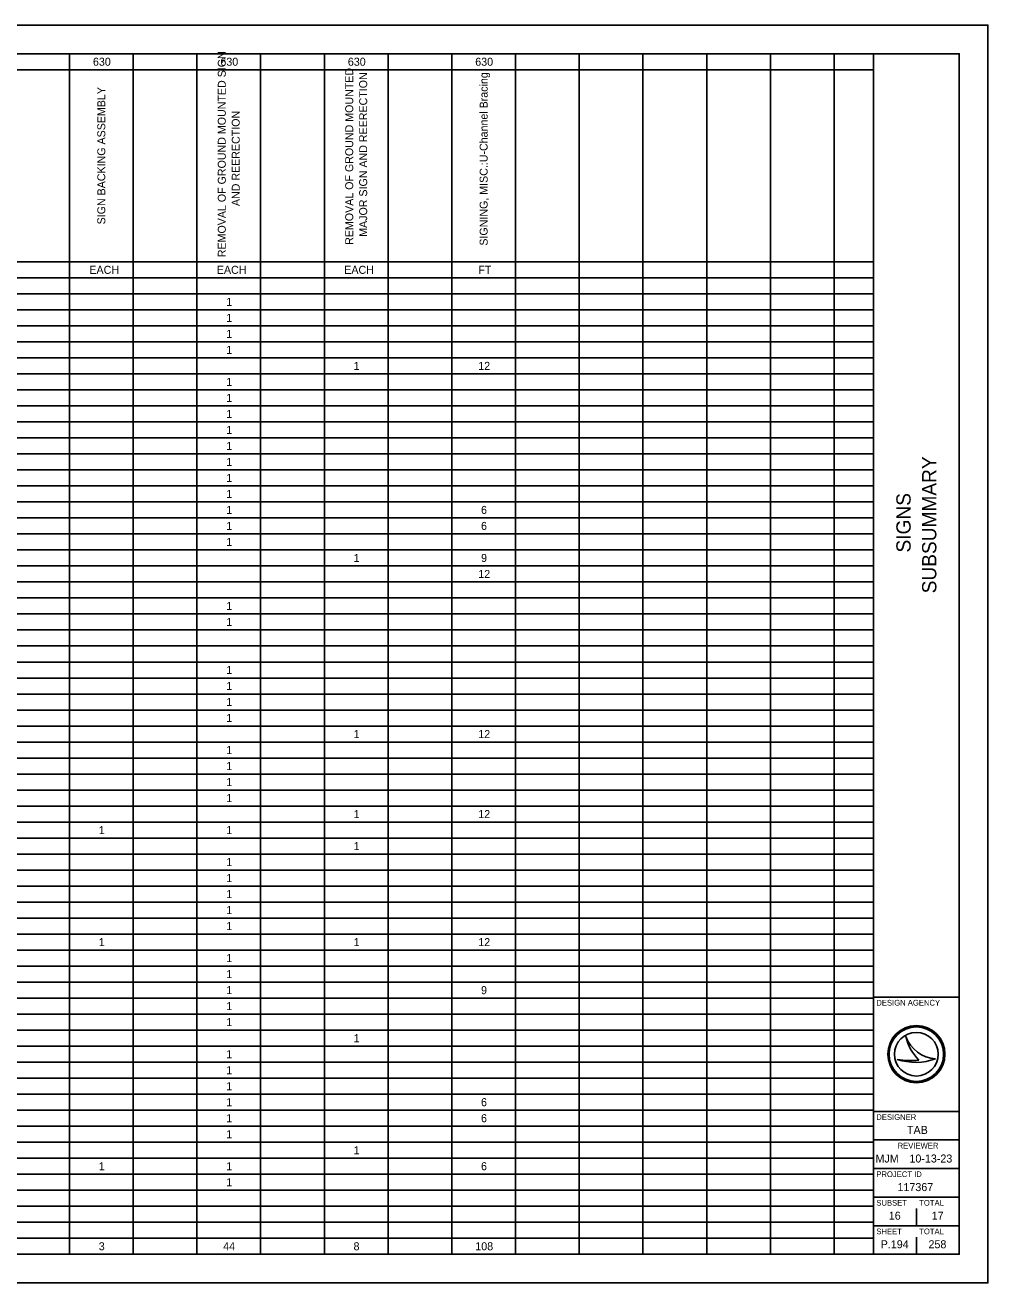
# Model space of a CAD drawing. Extents: x 0 to 34, y 0 to 22.
# Drawn here: x 17.16 to 34, y 0 to 22 of the extents above; entities that cross this region are included whole.
import ezdxf

# ---------------------------------------------------------------- set-up
doc = ezdxf.new("R2010")
doc.units = 0
for name, color, linetype in [('Default', 7, 'Continuous'), ('SH_Border', 7, 'Continuous'), ('SH_Cut_Line', 7, 'Continuous'), ('SH_Data', 7, 'Continuous')]:
    doc.layers.add(name, color=color, linetype=linetype)

msp = doc.modelspace()

# ---------------------------------------------------------------- linework, layer by layer
at = {"layer": 'Default'}
for p, q in [((1.5, 21.5), (32, 21.5)), ((17.938, 21.5), (17.938, 0.5)), ((19.053, 21.5), (19.053, 0.5)), ((20.167, 21.5), (20.167, 0.5)), ((21.282, 21.5), (21.282, 0.5)), ((22.396, 21.5), (22.396, 0.5)), ((23.51, 21.5), (23.51, 0.5)), ((24.625, 21.5), (24.625, 0.5)), ((25.739, 21.5), (25.739, 0.5)), ((26.854, 21.5), (26.854, 0.5)), ((27.968, 21.5), (27.968, 0.5)), ((29.083, 21.5), (29.083, 0.5)), ((30.197, 21.5), (30.197, 0.5)), ((31.312, 21.5), (31.312, 0.5)), ((32, 21.5), (32, 0.5)), ((8.646, 21.22), (32, 21.22)), ((8.646, 17.86), (32, 17.86)), ((1.5, 17.58), (32, 17.58)), ((1.5, 17.3), (32, 17.3)), ((1.5, 17.02), (32, 17.02)), ((1.5, 16.74), (32, 16.74)), ((1.5, 16.46), (32, 16.46)), ((1.5, 16.18), (32, 16.18)), ((1.5, 15.9), (32, 15.9)), ((1.5, 15.62), (32, 15.62)), ((1.5, 15.34), (32, 15.34)), ((1.5, 15.06), (32, 15.06)), ((1.5, 14.78), (32, 14.78)), ((1.5, 14.5), (32, 14.5)), ((1.5, 14.22), (32, 14.22)), ((1.5, 13.94), (32, 13.94)), ((1.5, 13.66), (32, 13.66)), ((1.5, 13.38), (32, 13.38)), ((1.5, 13.1), (32, 13.1)), ((1.5, 12.82), (32, 12.82)), ((1.5, 12.54), (32, 12.54)), ((1.5, 12.26), (32, 12.26)), ((1.5, 11.98), (32, 11.98)), ((1.5, 11.7), (32, 11.7)), ((1.5, 11.42), (32, 11.42)), ((1.5, 11.14), (32, 11.14)), ((1.5, 10.86), (32, 10.86)), ((1.5, 10.58), (32, 10.58)), ((1.5, 10.3), (32, 10.3)), ((1.5, 10.02), (32, 10.02)), ((1.5, 9.74), (32, 9.74)), ((1.5, 9.46), (32, 9.46)), ((1.5, 9.18), (32, 9.18)), ((1.5, 8.9), (32, 8.9)), ((1.5, 8.62), (32, 8.62)), ((1.5, 8.34), (32, 8.34)), ((1.5, 8.06), (32, 8.06)), ((1.5, 7.78), (32, 7.78)), ((1.5, 7.5), (32, 7.5)), ((1.5, 7.22), (32, 7.22)), ((1.5, 6.94), (32, 6.94)), ((1.5, 6.66), (32, 6.66)), ((1.5, 6.38), (32, 6.38)), ((1.5, 6.1), (32, 6.1)), ((1.5, 5.82), (32, 5.82)), ((1.5, 5.54), (32, 5.54)), ((1.5, 5.26), (32, 5.26)), ((1.5, 4.98), (32, 4.98)), ((1.5, 4.7), (32, 4.7)), ((1.5, 4.42), (32, 4.42)), ((1.5, 4.14), (32, 4.14)), ((1.5, 3.86), (32, 3.86)), ((1.5, 3.58), (32, 3.58)), ((1.5, 3.3), (32, 3.3)), ((1.5, 3.02), (32, 3.02)), ((1.5, 2.74), (32, 2.74)), ((1.5, 2.46), (32, 2.46)), ((1.5, 2.18), (32, 2.18)), ((1.5, 1.9), (32, 1.9)), ((1.5, 1.62), (32, 1.62)), ((1.5, 1.34), (32, 1.34)), ((1.5, 1.06), (32, 1.06)), ((1.5, 0.78), (32, 0.78)), ((1.5, 0.5), (32, 0.5))]:
    msp.add_line(p, q, dxfattribs=at)
at = {"layer": 'SH_Border'}
for p, q in [((32, 0.5), (32, 21.5)), ((32, 5), (33.5, 5)), ((32, 3), (33.5, 3)), ((32, 2.5), (33.5, 2.5)), ((32, 2), (33.5, 2)), ((32, 1.5), (33.5, 1.5)), ((32, 1), (33.5, 1))]:
    msp.add_line(p, q, dxfattribs=at)
msp.add_lwpolyline([(1.5, 21.5), (33.5, 21.5), (33.5, 0.5), (1.5, 0.5)], close=True, dxfattribs=at)
at = {"layer": 'SH_Cut_Line'}
msp.add_lwpolyline([(0, 0), (34, 0), (34, 22), (0, 22)], close=True, dxfattribs=at)
at = {"layer": 'SH_Data'}
for p, q in [((32.567, 4.31), (32.567, 4.31)), ((32.75, 4), (32.75, 4)), ((32.417, 3.91), (32.417, 3.91)), ((33.087, 3.919), (33.087, 3.919)), ((32.75, 1), (32.75, 1.3)), ((32.375, 0.675), (32.375, 0.675)), ((32.75, 0.5), (32.75, 0.8))]:
    msp.add_line(p, q, dxfattribs=at)
for radius in [0.5, 0.477, 0.477, 0.382]:
    msp.add_circle((32.75, 4), radius, dxfattribs=at)
for centre, radius, start, end in [((33.116, 4.498), 0.58, 198.9257, 198.9319), ((33.347, 4.47), 0.796, 191.6379, 191.6421), ((33.116, 4.498), 0.58, 198.9319, 267.1657), ((33.347, 4.47), 0.796, 191.6421, 226.0947), ((32.739, 4.87), 1.013, 251.4576, 290.0832), ((32.648, 5.154), 1.266, 259.4964, 259.4995), ((32.739, 4.87), 1.013, 251.4527, 251.4576), ((32.648, 5.154), 1.266, 259.4995, 276.6672)]:
    msp.add_arc(centre, radius, start, end, dxfattribs=at)

# ---------------------------------------------------------------- texts
at = {"layer": 'Default'}
for s, p in [('630', (18.349, 21.29)), ('630', (20.578, 21.29)), ('630', (22.807, 21.29)), ('630', (25.035, 21.29)), ('EACH', (18.286, 17.65)), ('EACH', (20.515, 17.65)), ('EACH', (22.744, 17.65)), ('FT', (25.089, 17.65)), ('1', (20.68, 17.09)), ('1', (20.68, 16.81)), ('1', (20.68, 16.53)), ('1', (20.68, 16.25)), ('1', (22.909, 15.97)), ('12', (25.088, 15.97)), ('1', (20.68, 15.69)), ('1', (20.68, 15.41)), ('1', (20.68, 15.13)), ('1', (20.68, 14.85)), ('1', (20.68, 14.57)), ('1', (20.68, 14.29)), ('1', (20.68, 14.01)), ('1', (20.68, 13.73)), ('1', (20.68, 13.45)), ('6', (25.136, 13.45)), ('1', (20.68, 13.17)), ('6', (25.136, 13.17)), ('1', (20.68, 12.89)), ('1', (22.909, 12.61)), ('9', (25.137, 12.61)), ('12', (25.088, 12.33)), ('1', (20.68, 11.77)), ('1', (20.68, 11.49)), ('1', (20.68, 10.65)), ('1', (20.68, 10.37)), ('1', (20.68, 10.09)), ('1', (20.68, 9.81)), ('1', (22.909, 9.53)), ('12', (25.088, 9.53)), ('1', (20.68, 9.25)), ('1', (20.68, 8.97)), ('1', (20.68, 8.69)), ('1', (20.68, 8.41)), ('1', (22.909, 8.13)), ('12', (25.088, 8.13)), ('1', (18.451, 7.85)), ('1', (20.68, 7.85)), ('1', (22.909, 7.57)), ('1', (20.68, 7.29)), ('1', (20.68, 7.01)), ('1', (20.68, 6.73)), ('1', (20.68, 6.45)), ('1', (20.68, 6.17)), ('1', (18.451, 5.89)), ('1', (22.909, 5.89)), ('12', (25.088, 5.89)), ('1', (20.68, 5.61)), ('1', (20.68, 5.33)), ('1', (20.68, 5.05)), ('9', (25.137, 5.05)), ('1', (20.68, 4.77)), ('1', (20.68, 4.49)), ('1', (22.909, 4.21)), ('1', (20.68, 3.93)), ('1', (20.68, 3.65)), ('1', (20.68, 3.37)), ('1', (20.68, 3.09)), ('6', (25.136, 3.09)), ('1', (20.68, 2.81)), ('6', (25.136, 2.81)), ('1', (20.68, 2.53)), ('1', (22.909, 2.25)), ('1', (18.451, 1.97)), ('1', (20.68, 1.97)), ('6', (25.136, 1.97)), ('1', (20.68, 1.69)), ('3', (18.451, 0.57)), ('44', (20.627, 0.57)), ('8', (22.907, 0.57)), ('108', (25.036, 0.57))]:
    msp.add_text(s, height=0.14, dxfattribs=at).set_placement(p)
for s, p in [('REMOVAL OF GROUND MOUNTED SIGN ', (20.672, 17.941)), ('REMOVAL OF GROUND MOUNTED ', (22.901, 18.157)), ('MAJOR SIGN AND REERECTION', (23.145, 18.298)), ('SIGNING, MISC.:U-Channel Bracing', (25.252, 18.143)), ('SIGN BACKING ASSEMBLY', (18.565, 18.515)), ('AND REERECTION', (20.916, 18.835))]:
    msp.add_text(s, height=0.13931, rotation=90, dxfattribs=at).set_placement(p)
at = {"layer": 'SH_Data'}
for s, p in [('SUBSUMMARY', (33.1, 12.061)), ('SIGNS', (32.65, 12.775))]:
    msp.add_text(s, height=0.25, rotation=90, dxfattribs=at).set_placement(p)
for s, height, p in [('DESIGN AGENCY', 0.1, (32.05, 4.85)), ('DESIGNER', 0.1, (32.05, 2.85)), ('TAB', 0.14, (32.586, 2.605)), ('REVIEWER', 0.1, (32.422, 2.35)), ('MJM', 0.14, (32.035, 2.105)), ('10-13-23', 0.14, (32.629, 2.105)), ('PROJECT ID', 0.1, (32.05, 1.85)), ('117367', 0.14, (32.42, 1.605)), ('SUBSET', 0.1, (32.05, 1.35)), ('TOTAL', 0.1, (32.8, 1.35)), ('16', 0.14, (32.268, 1.105)), ('17', 0.14, (33.018, 1.105)), ('SHEET', 0.1, (32.05, 0.85)), ('TOTAL', 0.1, (32.8, 0.85)), ('P.194', 0.14, (32.126, 0.605)), ('258', 0.14, (32.962, 0.605))]:
    msp.add_text(s, height=height, dxfattribs=at).set_placement(p)

doc.saveas('drawing.dxf')
